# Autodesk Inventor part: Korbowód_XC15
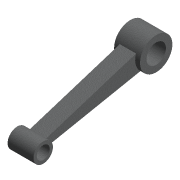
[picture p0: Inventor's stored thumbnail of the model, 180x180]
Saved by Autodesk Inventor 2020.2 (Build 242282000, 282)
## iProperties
Created: 2000-05
Part Number: Korbowód_XC15
Document SubType Name: Modeling
Designer: F.Stasiak
Stock Number: Korbowód_XC15
Density: 1 g/cm^3
Material: Default
Appearance: Aluminium (odlew)
Manager: www.cadconsulting.pl
Company: Fabian Stasiak CAD Consulting
Control State: 0
Master: False
Checked Out: False
Shininess: 0.0
Density: 0.0
Volumn: 0.0
Area: 0.0
PropertySet Name: Model Information
Author: F.Stasiak
Subject: Zbiór ćwiczeń. Autodesk Inventor 2020. Kurs podstawowy
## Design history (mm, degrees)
node "Base1"
node "Bryła1"
node "Korpusy bryłowe"
node "Korpusy powierzchniowe"
